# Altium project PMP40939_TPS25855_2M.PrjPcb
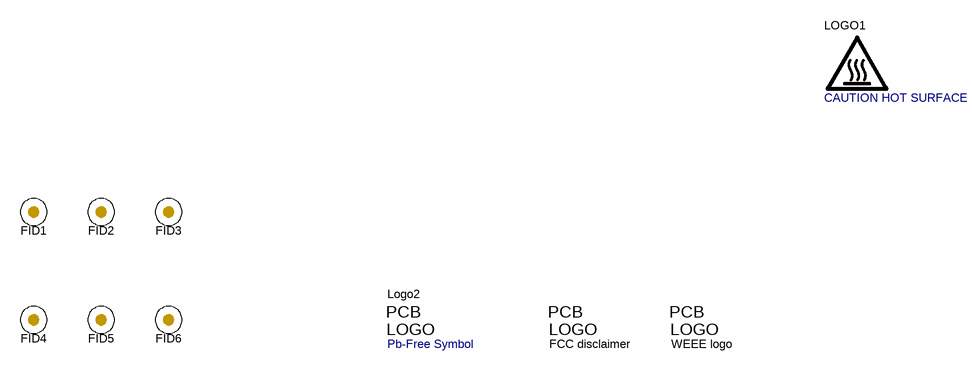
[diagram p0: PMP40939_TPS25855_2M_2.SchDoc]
TID: N/A; TechSupport: http://www.ti.com/support; SCH_Rev: E1; PRJ_Title: Change in menu Project|Project Options|Parameters; PRJ_Number: PMP40939; PRJ_Engineer: Pioneer Li; PRJ_Customer: Public Release; PCB_Rev: E1; PCB_Layout: Pioneer Li; CopyrightYear: 2021
2 sheets, 75 parts. Net scope: flat (ports and power ports of the same name join across sheets).
Board file: PMP40939_TPS25855_2M.PcbDoc
Sheets:
  PMP40939_TPS25855_2M_2.SchDoc
  PMP40939_TPS25855_2M_1.SchDoc

## Sheet PMP40939_TPS25855_2M_2.SchDoc
size 431 x 279 mm; Date: Not shown in title block; ApprovedBy: Not shown in title block; CheckedBy: Not shown in title block; Author: Not shown in title block; CompanyName: Not shown in title block; Engineer: Not shown in title block; Organization: Not shown in title block; Address1: Not shown in title block; Address2: Not shown in title block; Address3: Not shown in title block; Address4: Not shown in title block; DocumentNumber: 2; Revision: Use project parameter SCH_Rev; SheetNumber: 2; SheetTotal: 2; PageSetup: Record=PageOptions¦CenterHorizontal=True¦CenterVertical=True¦PrintScale=1.00¦XCorrection=1.00¦YCorrection=1.00¦PrintKind=0¦BorderSize=5000000¦LeftOffset=0¦BottomOffset=0¦Orientation=2¦PaperLength=1000¦PaperWidth=1000¦Scale=100¦PaperSource=15¦PrintQuality=600¦MediaType=1¦DitherType=10¦PaperKind=Letter¦PrintScaleMode=1

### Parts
FID1  Fiducial  [Fiducial10-20]  (value not drawn)
FID2  Fiducial  [Fiducial10-20]  (value not drawn)
FID3  Fiducial  [Fiducial10-20]  (value not drawn)
FID4  Fiducial  [Fiducial10-20]  (value not drawn)
FID5  Fiducial  [Fiducial10-20]  (value not drawn)
FID6  Fiducial  [Fiducial10-20]  (value not drawn)
LOGO1  CAUTION HOT SURFACE  [IEC_HotSurface_Small]  (no BOM)
Logo2  Pb-Free Symbol  [Pb-Free_Overlay_Medium]  (no BOM)
Logo3  FCC disclaimer  [FCC_disclaimer]  (no BOM)
Logo4  WEEE logo  [WEEE_Minimum]  (no BOM)

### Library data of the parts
FID1-FID6 = CMP-0077181-1: Fiducial mark.  There is nothing to buy or mount.
LOGO1 = CMP-0074837-1: IEC 61010-1 Hot Surface Warning; SymbolCreator: a0412235
Logo2 = CMP-0074839-1: SymbolCreator: a0412235
Logo3 = CMP-0074847-1: FCC_disclaimer; Library Reference: Logo
Logo4 = CMP-0074769-1

## Sheet PMP40939_TPS25855_2M_1.SchDoc
size 431 x 279 mm; Date: Not shown in title block; ApprovedBy: Not shown in title block; CheckedBy: Not shown in title block; Author: Not shown in title block; CompanyName: Not shown in title block; Engineer: Not shown in title block; Organization: Not shown in title block; Address1: Not shown in title block; Address2: Not shown in title block; Address3: Not shown in title block; Address4: Not shown in title block; DocumentNumber: 1; Revision: Use project parameter SCH_Rev; SheetNumber: 1; SheetTotal: 2; PageSetup: Record=PageOptions¦CenterHorizontal=True¦CenterVertical=True¦PrintScale=1.00¦XCorrection=1.00¦YCorrection=1.00¦PrintKind=0¦BorderSize=5000000¦LeftOffset=0¦BottomOffset=0¦Orientation=2¦PaperLength=1000¦PaperWidth=1000¦Scale=100¦PaperSource=15¦PrintQuality=600¦MediaType=1¦DitherType=10¦PaperKind=Letter¦PrintScaleMode=1
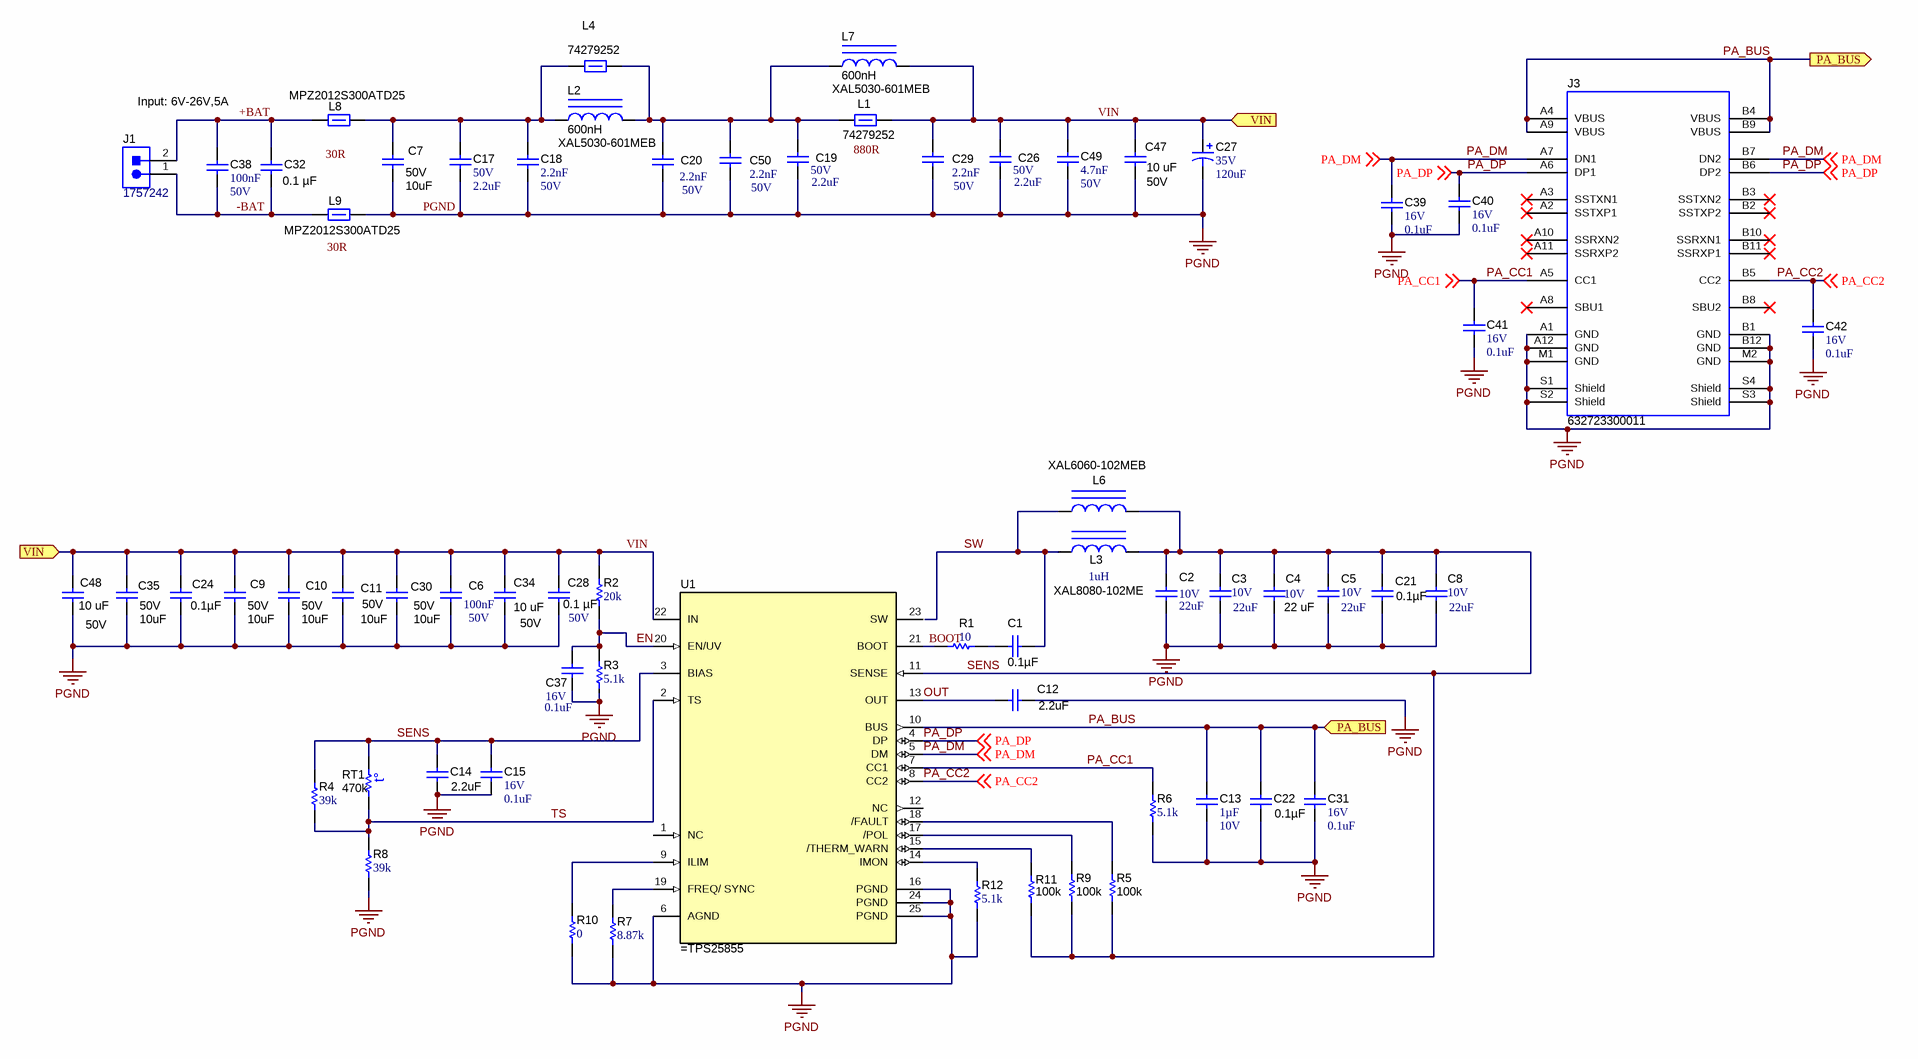
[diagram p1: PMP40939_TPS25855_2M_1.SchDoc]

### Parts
C1  ValueDisplayed: 0.1µF  [0603]  (hidden comment: C0603C104K5RACAUTO)
C2  VDC_V: 10V  ValueDisplayed: 22uF  [1206_180]  (hidden comment: GRM31CR71A226ME15L)
C3  VDC_V: 10V  ValueDisplayed: 22uF  [1206_180]  (hidden comment: GRM31CR71A226ME15L)
C4  22 uF  VDC_V: 10V  [1206_180]
C5  VDC_V: 10V  ValueDisplayed: 22uF  [1206_180]  (hidden comment: GRM31CR71A226ME15L)
C6  Cap_F: 100nF  VDC_V: 50V  [0805_HV]  (hidden comment: CL21B104MBCNNNC)
C7  VDC_V: 50V  ValueDisplayed: 10uF  [1206_180]  (hidden comment: GRT31CR61H106KE01L)
C8  VDC_V: 10V  ValueDisplayed: 22uF  [1206_180]  (hidden comment: GRM31CR71A226ME15L)
C9  VDC_V: 50V  ValueDisplayed: 10uF  [1206_180]  (hidden comment: GRT31CR61H106KE01L)
C10  VDC_V: 50V  ValueDisplayed: 10uF  [1206_180]  (hidden comment: GRT31CR61H106KE01L)
C11  VDC_V: 50V  ValueDisplayed: 10uF  [1206_180]  (hidden comment: GRT31CR61H106KE01L)
C12  ValueDisplayed: 2.2uF  [0603]  (hidden comment: 885012106018)
C13  Cap_F: 1µF  VDC_V: 10V  [0805_HV]  (hidden comment: C2012X7R1A106M125AC)
C14  ValueDisplayed: 2.2uF  [0603]  (hidden comment: 885012106018)
C15  VDC_V: 16V  ValueDisplayed: 0.1uF  [0402]  (hidden comment: GRM155R71C104JA88D)
C17  VDC_V: 50V  ValueDisplayed: 2.2uF  [1206_180]  (hidden comment: GCM31CR71H225KA55L)
C18  Cap_F: 2.2nF  VDC_V: 50V  [0603]  (hidden comment: C0603C222K5RACTU)
C19  VDC_V: 50V  ValueDisplayed: 2.2uF  [1206_180]  (hidden comment: GCM31CR71H225KA55L)
C20  Cap_F: 2.2nF  VDC_V: 50V  [0603]  (hidden comment: C0603C222K5RACTU)
C21  ValueDisplayed: 0.1µF  [0603]  (hidden comment: C0603C104K5RACAUTO)
C22  ValueDisplayed: 0.1µF  [0603]  (hidden comment: C0603C104K5RACAUTO)
C24  ValueDisplayed: 0.1µF  [0603]  (hidden comment: C0603C104K5RACAUTO)
C26  VDC_V: 50V  ValueDisplayed: 2.2uF  [1206_180]  (hidden comment: GCM31CR71H225KA55L)
C27  VDC_V: 35V  ValueDisplayed: 120uF  [SM_RADIAL_D8]  (hidden comment: EEHZKV121XUP)
C28  0.1 µF  VDC_V: 50V  [0805_HV]
C29  Cap_F: 2.2nF  VDC_V: 50V  [0603]  (hidden comment: C0603C222K5RACTU)
C30  VDC_V: 50V  ValueDisplayed: 10uF  [1206_180]  (hidden comment: GRT31CR61H106KE01L)
C31  VDC_V: 16V  ValueDisplayed: 0.1uF  [0402]  (hidden comment: GRM155R71C104JA88D)
C32  0.1 µF  [0603]
C34  10 uF  VDC_V: 50V  [1206_180]
C35  VDC_V: 50V  ValueDisplayed: 10uF  [1206_180]  (hidden comment: GRT31CR61H106KE01L)
C37  VDC_V: 16V  ValueDisplayed: 0.1uF  [0402]  (hidden comment: C0402C104K4RACAUTO)
C38  Cap_F: 100nF  VDC_V: 50V  [0805_150]  (hidden comment: CEU4J2X7R1H104K125AE)
C39  VDC_V: 16V  ValueDisplayed: 0.1uF  [0402]  (hidden comment: GRM155R71C104JA88D)
C40  VDC_V: 16V  ValueDisplayed: 0.1uF  [0402]  (hidden comment: GRM155R71C104JA88D)
C41  VDC_V: 16V  ValueDisplayed: 0.1uF  [0402]  (hidden comment: GRM155R71C104JA88D)
C42  VDC_V: 16V  ValueDisplayed: 0.1uF  [0402]  (hidden comment: GRM155R71C104JA88D)
C47  10 uF  VDC_V: 50V  [1206_180]
C48  10 uF  VDC_V: 50V  [1206_180]
C49  Cap_F: 4.7nF  VDC_V: 50V  [0603]  (hidden comment: GCM188R71H472KA37D)
C50  Cap_F: 2.2nF  VDC_V: 50V  [0603]  (hidden comment: C0603C222K5RACTU)
J1  1757242  [PHOENIX_1757242]
J3  632723300011  [Wurth_632_723_300_011]
L1  74279252  [1812_170_HighSpeed]
L2  XAL5030-601MEB  ValueDisplayed: 600nH  [XAL5030]
L3  XAL8080-102ME  [XAL8080]
L4  74279252  [1812_170_HighSpeed]
L6  XAL6060-102MEB  ValueDisplayed: 1uH  [XAL6060]
L7  XAL5030-601MEB  ValueDisplayed: 600nH  [XAL5030]
L8  MPZ2012S300ATD25  [1206]
L9  MPZ2012S300ATD25  [1206]
R1  ValueDisplayed: 10  [0603]  (hidden comment: CRCW060310R0JNEA)
R2  ValueDisplayed: 20k  [0402]  (hidden comment: CRCW040220K0JNED)
R3  ValueDisplayed: 5.1k  [0402]  (hidden comment: CRCW04025K10JNED)
R4  ValueDisplayed: 39k  [0402]  (hidden comment: ERJ-2GEJ393X)
R5  ValueDisplayed: 100k  [0603]  (hidden comment: CRCW0603100KFKEA)
R6  ValueDisplayed: 5.1k  [0402]  (hidden comment: CRCW04025K10JNED)
R7  ValueDisplayed: 8.87k  [0402]  (hidden comment: CRCW04028K87FKED)
R8  ValueDisplayed: 39k  [0402]  (hidden comment: ERJ-2GEJ393X)
R9  ValueDisplayed: 100k  [0603]  (hidden comment: CRCW0603100KFKEA)
R10  ValueDisplayed: 0  [0402]  (hidden comment: MCR01MZPJ000)
R11  ValueDisplayed: 100k  [0603]  (hidden comment: CRCW0603100KFKEA)
R12  ValueDisplayed: 5.1k  [0402]  (hidden comment: CRCW04025K10JNED)
RT1  value 470k  [0603S]  (hidden comment: NCP18WM474J03RB)
U1  (no value)  [RPQ0025A]

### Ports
PA_BUS (in), PA_BUS (out), VIN (in)

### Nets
PGND: C2.2 C3.2 C4.2 C5.2 C6.2 C7.2 C8.2 C9.2 C10.2 C11.2 C12.2 C13.2 C14.2 C15.2 C17.2 C18.2 C19.2 C20.2 C21.2 C22.2 C24.2 C26.2 C27.2(-) C28.2 C29.2 C30.2 C31.2 C34.2 C35.2 C37.2 C39.2 C40.2 C41.2 C42.2 C47.2 C48.2 C49.2 C50.2 J3.A1(GND) J3.A12(GND) J3.B1(GND) J3.B12(GND) J3.M1(GND) J3.M2(GND) J3.S1(Shield) J3.S2(Shield) J3.S3(Shield) J3.S4(Shield) L9.2 R3.1 R6.1 R7.1 R8.1 R10.1 R12.1 U1.6(AGND) U1.16(PGND) U1.24(PGND) U1.25(PGND)
+BAT: C32.1 C38.1 J1.2 L8.1
-BAT: C32.2 C38.2 J1.1 L9.1
BOOT: R1.1 U1.21(BOOT)
EN: C37.1 R2.1 R3.2 U1.20(EN/UV)
OUT: C12.1 U1.13(OUT)
PA_BUS: C13.1 C22.1 C31.1 J3.A4(VBUS) J3.A9(VBUS) J3.B4(VBUS) J3.B9(VBUS) U1.10(BUS) ; port PA_BUS
PA_CC1: C41.1 J3.A5(CC1) R6.2 U1.7(CC1) ; off-sheet PA_CC1
PA_CC2: C42.1 J3.B5(CC2) U1.8(CC2) ; off-sheet PA_CC2
PA_DM: C39.1 J3.A7(DN1) J3.B7(DN2) U1.5(DM) ; off-sheet PA_DM
PA_DP: C40.1 J3.A6(DP1) J3.B6(DP2) U1.4(DP) ; off-sheet PA_DP
SENS: C2.1 C3.1 C4.1 C5.1 C8.1 C14.1 C15.1 C21.1 L3.2 L6.2 R4.2 R5.1 R9.1 R11.1 RT1.2 U1.3(BIAS) U1.11(SENSE)
SW: C1.1 L3.1 L6.1
TS: R4.1 R8.2 RT1.1 U1.2(TS)
VIN: C6.1 C9.1 C10.1 C11.1 C24.1 C26.1 C27.1(+) C28.1 C29.1 C30.1 C34.1 C35.1 C47.1 C48.1 C49.1 L1.2 L7.2 R2.2 U1.22(IN) ; port VIN
NetC1_2: C1.2 R1.2
NetC7_1: C7.1 C17.1 C18.1 L2.1 L4.1 L8.2
NetC19_1: C19.1 C20.1 C50.1 L1.1 L2.2 L4.2 L7.1
NetR5_2: R5.2 U1.18(/FAULT)
NetR7_2: R7.2 U1.19(FREQ/_SYNC)
NetR9_2: R9.2 U1.17(/POL)
NetR10_2: R10.2 U1.9(ILIM)
NetR11_2: R11.2 U1.15(/THERM_WARN)
NetR12_2: R12.2 U1.14(IMON)

Not connected (* = marked no-connect by the designer): J3 A2(SSTXP1)* A3(SSTXN1)* A8(SBU1)* A10(SSRXN2)* A11(SSRXP2)* B2(SSTXP2)* B3(SSTXN2)* B8(SBU2)* B10(SSRXN1)* B11(SSRXP1)*; U1 1(NC) 12(NC) 23(SW)

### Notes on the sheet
- Input: 6V-26V,5A
- Labels drawn without touching a wire or pin: 30R, 880R, FREQ, ILIM

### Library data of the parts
C1 C21 C22 C24 = CMP-0079602-1: CAP, CERM, 0.1 µF, 50 V,+/- 10%, X7R, AEC-Q200 Grade 1, 0603; Manufacturer: Kemet; TaMin_C: -55°C; Polarized: N; SizeAreaWB_mm2: 4.68; U/M: EA; Value: 0.1uF; TaMax_C: 125°C; SizeZ_mm: 1; SizeX_mm: 1.6; SizeY_mm: 0.8; Value2: 50V; SizeArea_mm2: 1.28; CompType: Capacitor; AEC Qualified: Y; Cap_F: 100nF; AEC Category: Q200
C2 C3 C5 C8 = CMP-0008960-2: CAP, CERM, 22 uF, 10 V, +/- 20%, X7R, 1206; Manufacturer: MuRata; TaMin_C: -55°C; Polarized: N; SizeAreaWB_mm2: 10.92; Value1: Unknown; U/M: EA; Value: 22uF; TaMax_C: 125°C; SizeZ_mm: 1.8; SizeX_mm: 3.2; SizeY_mm: 1.6; Cap_Case: 1206; SizeArea_mm2: 5.12; Cap_F: 22µF; AEC Category: Q200
C4 = CMP-0008960-2: CAP, CERM, 22 uF, 10 V, +/- 20%, X7R, 1206; Manufacturer: MuRata; PartNumber: GRM31CR71A226ME15L; TaMin_C: -55°C; Polarized: N; SizeAreaWB_mm2: 10.92; Value1: Unknown; U/M: EA; Value: 22uF; TaMax_C: 125°C; SizeZ_mm: 1.8; SizeX_mm: 3.2; SizeY_mm: 1.6; Cap_Case: 1206; SizeArea_mm2: 5.12; Cap_F: 22µF; AEC Category: Q200
C6 = CMP-0082524-1: CAP, CERM, 0.1 µF, 50 V,+/- 20%, X7R, 0805; Manufacturer: Samsung; SizeAreaWB_mm2: 6.75; SizeArea_mm2: 2.5; AEC Qualified: N; AEC Category: Q200; Value: 0.1uF; TaMax_C: 125°C; SizeZ_mm: 1.45; TaMin_C: -55°C; SizeY_mm: 1.25; U/M: EA; SizeX_mm: 2; Cap_Case: 0805; ValueDisplayed: 0.1µF
C7 C9-C11 C30 C35 = CMP-0009015-1: CAP, CERM, 10 uF, 50 V, +/- 10%, X5R, AEC-Q200 Grade 1, 1206; Manufacturer: MuRata; TaMin_C: -55°C; Polarized: N; SizeAreaWB_mm2: 10.92; Value1: Unknown; U/M: EA; Value: 10uF; TaMax_C: 85°C; SizeZ_mm: 1.8; SizeX_mm: 3.2; SizeY_mm: 1.6; Cap_Case: 1206; SizeArea_mm2: 5.12; AEC Qualified: Y; Cap_F: 10µF; AEC Grade: 1; AEC Category: Q200
C12 C14 = CMP-0006825-5: CAP, CERM, 2.2 uF, 16 V, +/- 20%, X5R, 0603; Manufacturer: Wurth Elektronik; TaMin_C: -55°C; Polarized: N; SizeAreaWB_mm2: 4.68; Value1: Unknown; U/M: EA; Value: 2.2uF; TaMax_C: 85°C; SizeZ_mm: 1; SizeX_mm: 1.6; SizeY_mm: 0.8; Value2: 16V; SizeArea_mm2: 1.28; CompType: Capacitor; Cap_F: 2.2µF; AEC Category: Q200
C13 = CMP-0007864-2: CAP, CERM, 10 uF, 10 V, +/- 20%, X7R, 0805; Manufacturer: TDK; TaMin_C: -55°C; Polarized: N; SizeAreaWB_mm2: 6.75; Value1: Unknown; U/M: EA; Value: 10uF; TaMax_C: 125°C; SizeZ_mm: 1.45; SizeX_mm: 2; SizeY_mm: 1.25; Cap_Case: 0805; SizeArea_mm2: 2.5; AEC Category: Q200
C15 C31 C39-C42 = CMP-0006640-2: CAP, CERM, 0.1 uF, 16 V, +/- 5%, X7R, 0402; Manufacturer: MuRata; TaMin_C: -55°C; Polarized: N; SizeAreaWB_mm2: 3; Value1: Unknown; U/M: EA; Value: 0.1uF; TaMax_C: 125°C; SizeZ_mm: 0.6; SizeX_mm: 1; SizeY_mm: 0.5; Cap_F: 100nF; AEC Category: Q200
C17 C19 C26 = CMP-0008814-2: CAP, CERM, 2.2 uF, 50 V, +/- 10%, X7R, AEC-Q200 Grade 1, 1206; Manufacturer: MuRata; TaMin_C: -55°C; Polarized: N; SizeAreaWB_mm2: 10.92; Value1: Unknown; U/M: EA; Value: 2.2uF; TaMax_C: 125°C; SizeZ_mm: 1.8; SizeX_mm: 3.2; SizeY_mm: 1.6; Cap_Case: 1206; SizeArea_mm2: 5.12; AEC Qualified: Y; Cap_F: 2.2µF; AEC Grade: 1; AEC Category: Q200
C18 C20 C29 C50 = CMP-0006898-4: CAP, CERM, 2200 pF, 50 V, +/- 10%, X7R, 0603; Manufacturer: Kemet; TaMin_C: -55°C; Polarized: N; SizeAreaWB_mm2: 4.68; Value1: Unknown; U/M: EA; Value: 2200pF; TaMax_C: 125°C; SizeZ_mm: 1; SizeX_mm: 1.6; SizeY_mm: 0.8; SizeArea_mm2: 1.28; AEC Category: Q200
C27 = CMP-0010724-1: CAP, AL, 120 uF, 35 V, +/- 20%, 0.035 ohm, AEC-Q200 , SMD; Manufacturer: Panasonic; TaMin_C: -55°C; ESR_ohm: 0.035; Polarized: Y; SizeAreaWB_mm2: 84.28; Value: 120uF; TaMax_C: 125°C; SizeZ_mm: 7.7; SizeX_mm: 7.8; SizeY_mm: 6.6; Cap_Case: D8; SizeArea_mm2: 51.48; CompType: Capacitor; IRMS_A: 1.7A; AEC Category: Q200
C28 = CMP-0082524-1: CAP, CERM, 0.1 µF, 50 V,+/- 20%, X7R, 0805; PartNumber: CL21B104MBCNNNC; Manufacturer: Samsung; SizeAreaWB_mm2: 6.75; SizeArea_mm2: 2.5; AEC Qualified: N; AEC Category: Q200; Value: 0.1uF; TaMax_C: 125°C; SizeZ_mm: 1.45; TaMin_C: -55°C; SizeY_mm: 1.25; U/M: EA; SizeX_mm: 2; Cap_Case: 0805; ValueDisplayed: 0.1µF
C32 = CMP-0079602-1: CAP, CERM, 0.1 µF, 50 V,+/- 10%, X7R, AEC-Q200 Grade 1, 0603; Manufacturer: Kemet; PartNumber: C0603C104K5RACAUTO; TaMin_C: -55°C; Polarized: N; SizeAreaWB_mm2: 4.68; U/M: EA; Value: 0.1uF; TaMax_C: 125°C; SizeZ_mm: 1; SizeX_mm: 1.6; SizeY_mm: 0.8; Value2: 50V; SizeArea_mm2: 1.28; CompType: Capacitor; AEC Qualified: Y; Cap_F: 100nF; AEC Category: Q200
C34 C47 C48 = CMP-0009015-1: CAP, CERM, 10 uF, 50 V, +/- 10%, X5R, AEC-Q200 Grade 1, 1206; Manufacturer: MuRata; PartNumber: GRT31CR61H106KE01L; TaMin_C: -55°C; Polarized: N; SizeAreaWB_mm2: 10.92; Value1: Unknown; U/M: EA; Value: 10uF; TaMax_C: 85°C; SizeZ_mm: 1.8; SizeX_mm: 3.2; SizeY_mm: 1.6; Cap_Case: 1206; SizeArea_mm2: 5.12; AEC Qualified: Y; Cap_F: 10µF; AEC Grade: 1; AEC Category: Q200
C37 = CMP-0006237-2: CAP, CERM, 0.1 uF, 16 V, +/- 10%, X7R, AEC-Q200 Grade 1, 0402; Manufacturer: Kemet; TaMin_C: -55°C; Polarized: N; SizeAreaWB_mm2: 3; Value1: Unknown; U/M: EA; Value: 0.1uF; TaMax_C: 125°C; SizeZ_mm: 0.6; SizeX_mm: 1; SizeY_mm: 0.5; AEC Qualified: Y; Cap_F: 100nF; AEC Category: Q200
C38 = CMP-0007961-2: CAP, CERM, 0.1 uF, 50 V, +/- 10%, X7R, AEC-Q200 Grade 1, 0805; Manufacturer: TDK; TaMin_C: -55°C; Polarized: N; SizeAreaWB_mm2: 6.75; Value1: Unknown; U/M: EA; Value: 0.1uF; TaMax_C: 125°C; SizeZ_mm: 1.5; SizeX_mm: 2; SizeY_mm: 1.25; Cap_Case: 0805; SizeArea_mm2: 2.5; AEC Qualified: Y; AEC Grade: 1; AEC Category: Q200
C49 = CMP-0007146-4: CAP, CERM, 4700 pF, 50 V, +/- 10%, X7R, AEC-Q200 Grade 1, 0603; Manufacturer: MuRata; TaMin_C: -55°C; Polarized: N; SizeAreaWB_mm2: 4.68; Value1: Unknown; U/M: EA; Value: 4700pF; TaMax_C: 125°C; SizeZ_mm: 1; SizeX_mm: 1.6; SizeY_mm: 0.8; SizeArea_mm2: 1.28; AEC Qualified: Y; AEC Category: Q200
J1 = CMP-0055534-1: Header (Shrouded), 5.08 mm, 2x1, Tin, R/A, TH; Manufacturer: Phoenix Contact; CT: FALSE
J3 = CMP-0080891-1: Connector, Receptacle, USB Type C, R/A; Manufacturer: Wurth Elektronik; Current_A: 3A; Gender: Female; Voltage_V: 5V; ContactFinish: Gold; Cert_UL: Y
L1 L4 = CMP-0003170-1: Ferrite Bead, 880 ohm @ 100 MHz, 4 A, 1812; Manufacturer: Wurth Elektronik; Ztyp@1GHz_Ohm: 80.561; ZTyp@100MHz_Ohm: 880; SizeAreaWB_mm2: 23.1; DCR_ohm: 0.035; Value1: 0.035 ohm; Value: 880 ohm; Imax_A: 4A; SizeZ_mm: 1.7; SizeX_mm: 4.5; SizeY_mm: 3.2; SizeArea_mm2: 14.4
L2 L7 = CMP-0061005-2: Inductor, Shielded, Composite, 600 nH, 17.7 A, 0.00411 ohm, AEC-Q200 Grade 1, SMD; Manufacturer: Coilcraft; Isat: 19.8A @ 30% inductance drop; Irms: 17.7A @ 40C rise; Green_Lifecycle: Not Set; SizeAreaWB_mm2: 54.4544; DCR_ohm: 4.11m; Green_REACh: Incomplete; Value: 600nH; Imax_A: 17.7A; SizeZ_mm: 3.1; SizeX_mm: 5.28; SizeY_mm: 5.48; SizeArea_mm2: 28.9344; AEC Qualified: 1; AEC Category: Q200; AEC Grade: Y
L3 = CMP-0061062-1: Inductor, Shielded, Composite, 4.7 uH, 10.5 A, 0.00889 ohm, SMD; Manufacturer: Coilcraft; PartNumber: XAL8080-472ME; Isat: 17.4A @ 20% inductance drop; Irms: 10.5A @ 20C rise; Green_Lifecycle: Not Set; SizeAreaWB_mm2: 107.06; DCR_ohm: 8.89m; Green_REACh: Incomplete; Value: 4.7uH; Imax_A: 10.5A; SizeZ_mm: 8; SizeX_mm: 8.1; SizeY_mm: 8.6; SizeArea_mm2: 69.66; Ind_H: 4.7µH; AEC Category: Q200
L6 = CMP-0061020-2: Inductor, Shielded, Composite, 4.7 µH, 10.5 A, 0.0144 ohm, AEC-Q200 Grade 1, SMD; Manufacturer: Coilcraft; PartNumber: XAL6060-472MEB; SizeZ_mm: 6.1; Ind_H: 4.7µH; AEC Qualified: Y; Imax_A: 10.5A; Value: 4.7uH; SizeY_mm: 6.56; AEC Category: Q200; SizeAreaWB_mm2: 71.5616; Green_REACh: Incomplete; DCR_ohm: 0.0144; Isat: 10.5A @ 30% inductance drop; Green_Lifecycle: Not Set; SizeX_mm: 6.36; SizeArea_mm2: 41.7216; AEC Grade: 1; Irms: 12.3A @ 40C rise
L8 L9 = CMP-0003139-1: Ferrite Bead, 30ohm @ 100 MHz, 6 A, 0805; Manufacturer: TDK; ZTyp@100MHz_Ohm: 30; DCR_ohm: 10 m; Value1: 0.010 ohm; Imax_A: 6A; SizeZ_mm: 0.85; SizeX_mm: 2.0; SizeY_mm: 1.25
R1 = CMP-0025703-4: RES, 10, 5%, 0.1 W, AEC-Q200 Grade 0, 0603; Manufacturer: Vishay-Dale; Power_W: 100mW; TempCo: 200 ppm/C; Value_Code: 10R0; Value: 10; EIA_Code: E24; SizeX_mm: 1.6; SizeY_mm: 0.8; SizeZ_mm: 1; Value2: 0.1W; SizeArea_mm2: 1.28; AEC Qualified: Y; VDC_V: 75V; AEC Category: Q200; AEC Grade: 0
R2 = CMP-0026875-3: RES, 20 k, 5%, 0.063 W, AEC-Q200 Grade 0, 0402; Manufacturer: Vishay-Dale; Power_W: 63mW; TempCo: 200 ppm/C; Value_Code: 20k0; Value: 20k; EIA_Code: E24; SizeX_mm: 1; SizeY_mm: 0.5; SizeZ_mm: 0.6; Value2: 0.063W; AEC Qualified: Y; VDC_V: 50V; AEC Category: Q200; AEC Grade: 0
R3 R6 R12 = CMP-0026951-5: RES, 5.1 k, 5%, 0.063 W, AEC-Q200 Grade 0, 0402; Manufacturer: Vishay-Dale; Power_W: 63mW; TempCo: 200 ppm/C; Value_Code: 5k10; Value: 5.1k; EIA_Code: E24; SizeX_mm: 1; SizeY_mm: 0.5; SizeZ_mm: 0.6; Value2: 0.063W; AEC Qualified: Y; VDC_V: 50V; AEC Category: Q200; AEC Grade: 0
R4 R8 = CMP-0026998-2: RES, 39 k, 5%, 0.1 W, AEC-Q200 Grade 0, 0402; Manufacturer: Panasonic; Power_W: 100mW; TempCo: 200 ppm/C; Value_Code: 39k0; U/M: EA; Value: 39k; EIA_Code: E24; SizeX_mm: 1; SizeY_mm: 0.5; SizeZ_mm: 0.6; Value2: 0.1W; AEC Qualified: Y; VDC_V: 50V; AEC Grade: 0; AEC Category: Q200
R5 R9 R11 = CMP-0021990-1: RES, 100 k, 1%, 0.1 W, 0603; Manufacturer: Vishay-Dale; Power_W: 100mW; TempCo: 100 ppm/C; U/M: EA; Value: 100k; EIA_Code: E96; SizeX_mm: 1.6; SizeY_mm: 0.8; SizeZ_mm: 1; Value2: 0.1W; SizeArea_mm2: 1.28; VDC_V: 75V; AEC Category: Q200
R7 = CMP-0026592-2: RES, 8.87 k, 1%, 0.063 W, AEC-Q200 Grade 0, 0402; Manufacturer: Vishay-Dale; Power_W: 63mW; TempCo: 100 ppm/C; Value_Code: 8k87; Value: 8.87k; EIA_Code: E96; SizeX_mm: 1; SizeY_mm: 0.5; SizeZ_mm: 0.6; Value2: 0.063W; AEC Qualified: Y; VDC_V: 50V; AEC Category: Q200; AEC Grade: 0
R10 = CMP-0027002-2: RES, 0, 5%, 0.063 W, 0402; Manufacturer: Rohm; Power_W: 63mW; TempCo: 500 ppm/C; Value_Code: 0000; U/M: EA; Value: 0; EIA_Code: E24; SizeX_mm: 1; SizeY_mm: 0.5; SizeZ_mm: 0.6; Value2: 0.063W; VDC_V: 50V; AEC Category: Q200
RT1 = CMP-0002545-3: Thermistor NTC, 470k ohm, 5%, 0603; Manufacturer: MuRata; TaMax_C: 125°C; SizeX_mm: 1.6; SizeY_mm: 0.8; TaMin_C: -40°C; Power_W: 100mW; SizeZ_mm: 1; SizeArea_mm2: 1.28; SizeAreaWB_mm2: 4.68; U/M: EA
U1 = Component_1: Manufacturer: Used in BOM report; CompType: Used in some BOM reports.  Useful for finding later.

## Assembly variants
001: not fitted C4 C26 C29 C32 C47 C48 C50 FID1 FID2 FID3 L4 L6 L7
